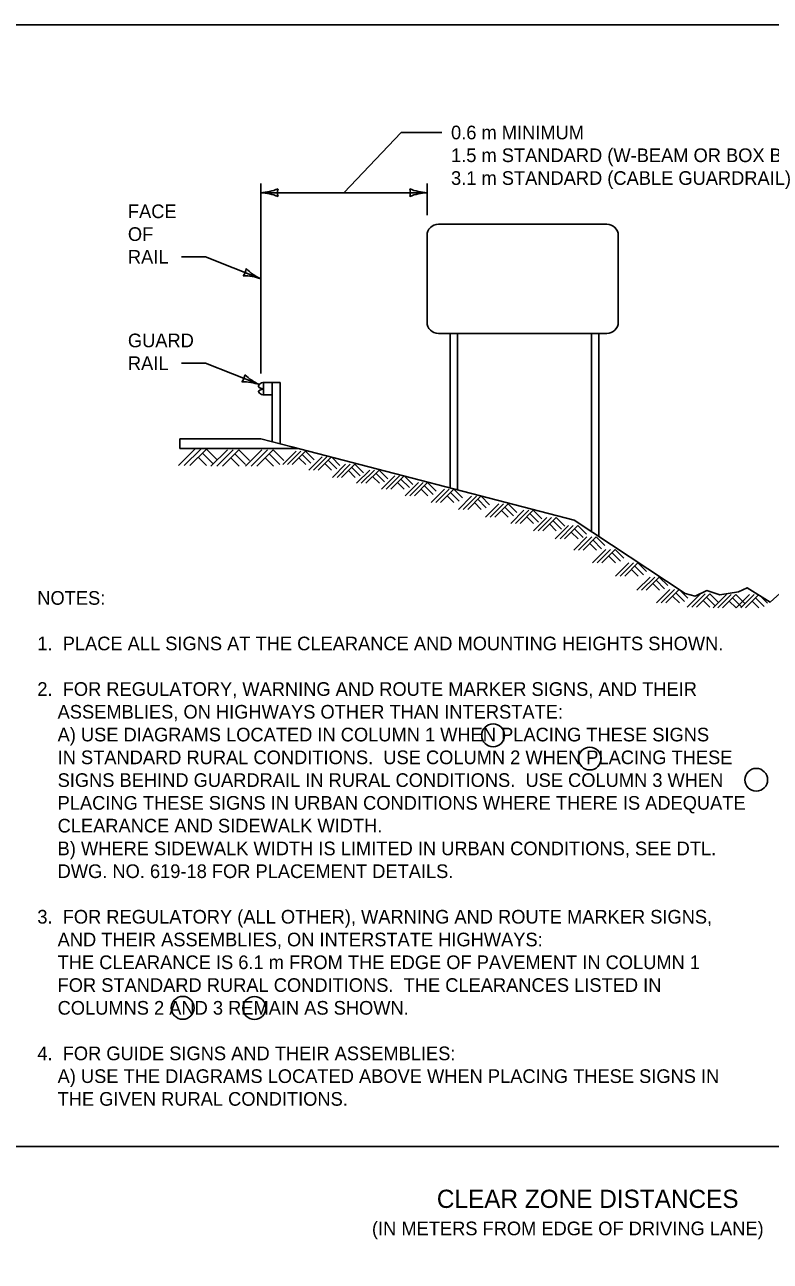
# Model space of a CAD drawing. Extents: x 49991.4 to 50021, y 49987.6 to 50011.4.
# Drawn here: x 50008.27 to 50011.55, y 49993.57 to 49999 of the extents above; entities that cross this region are included whole.
import ezdxf

# ---------------------------------------------------------------- set-up
doc = ezdxf.new("R2010")
doc.units = 0
for name, color, linetype in [('Level 1', 7, 'Continuous'), ('Level 2', 7, 'Continuous'), ('Level 3', 7, 'Continuous')]:
    doc.layers.add(name, color=color, linetype=linetype)

msp = doc.modelspace()

# ---------------------------------------------------------------- linework, layer by layer
at = {"layer": 'Level 1'}
for p, q in [((50010.8306, 49998.1235), (50010.0905, 49998.1235)), ((50010.0405, 49998.0735), (50010.0405, 49997.6934)), ((50010.8806, 49997.6934), (50010.8806, 49998.0735)), ((50010.0905, 49997.6434), (50010.8306, 49997.6434)), ((50010.1417, 49996.9646), (50010.1417, 49997.6434)), ((50010.1738, 49996.9562), (50010.1738, 49997.6434)), ((50010.7629, 49996.7725), (50010.7629, 49997.6434)), ((50010.795, 49996.7514), (50010.795, 49997.6434)), ((50009.3603, 49997.4275), (50009.3197, 49997.4275)), ((50009.3215, 49997.4275), (50009.3215, 49997.3742)), ((50009.3603, 49997.1675), (50009.3603, 49997.4275)), ((50009.3957, 49997.4275), (50009.3603, 49997.4275)), ((50009.3957, 49997.1586), (50009.3957, 49997.4275)), ((50009.3197, 49997.3742), (50009.3603, 49997.3742)), ((50008.9487, 49997.0636), (50009.0207, 49997.1356)), ((50009.31, 49997.1809), (50008.9538, 49997.1809)), ((50008.9538, 49997.1809), (50008.9538, 49997.1383)), ((50008.9538, 49997.1383), (50009.4739, 49997.1383)), ((50008.974, 49997.0636), (50009.046, 49997.1356)), ((50008.9991, 49997.0636), (50009.0711, 49997.1356)), ((50009.0711, 49997.1356), (50009.118, 49997.0888)), ((50009.0912, 49997.0606), (50009.1632, 49997.1326)), ((50009.1165, 49997.0606), (50009.1885, 49997.1326)), ((50009.1416, 49997.0606), (50009.2136, 49997.1326)), ((50009.2136, 49997.1326), (50009.2605, 49997.0858)), ((50009.2425, 49997.0606), (50009.3145, 49997.1326)), ((50009.2678, 49997.0606), (50009.3398, 49997.1326)), ((50009.2929, 49997.0606), (50009.3649, 49997.1326)), ((50009.446, 49997.1455), (50009.31, 49997.1809)), ((50009.3649, 49997.1326), (50009.4118, 49997.0858)), ((50009.446, 49997.1455), (50010.6864, 49996.8229)), ((50009.4737, 49997.1383), (50009.4737, 49997.1383)), ((50009.0355, 49997.0999), (50009.0719, 49997.0636)), ((50009.0534, 49997.1178), (50009.1002, 49997.0711)), ((50009.178, 49997.0969), (50009.2144, 49997.0606)), ((50009.1958, 49997.1148), (50009.2426, 49997.0681)), ((50009.3293, 49997.0969), (50009.3657, 49997.0606)), ((50009.3471, 49997.1148), (50009.3939, 49997.0681)), ((50009.4076, 49997.0684), (50009.4659, 49997.1267)), ((50009.4281, 49997.0684), (50009.4864, 49997.1267)), ((50009.4484, 49997.0684), (50009.5067, 49997.1267)), ((50009.4779, 49997.0979), (50009.5075, 49997.0684)), ((50009.4923, 49997.1124), (50009.5303, 49997.0745)), ((50009.5067, 49997.1267), (50009.5447, 49997.0888)), ((50009.5209, 49997.0431), (50009.5792, 49997.1014)), ((50009.5414, 49997.0431), (50009.5997, 49997.1014)), ((50009.5617, 49997.0431), (50009.6192, 49997.1005)), ((50009.6057, 49997.0871), (50009.6436, 49997.0492)), ((50009.6217, 49997.0998), (50009.658, 49997.0635)), ((50009.5912, 49997.0725), (50009.6208, 49997.0431)), ((50009.6246, 49997.0115), (50009.6829, 49997.0698)), ((50009.6451, 49997.0115), (50009.7034, 49997.0698)), ((50009.6654, 49997.0115), (50009.7237, 49997.0698)), ((50009.6949, 49997.041), (50009.7244, 49997.0115)), ((50009.7094, 49997.0555), (50009.7473, 49997.0176)), ((50009.7237, 49997.0698), (50009.7617, 49997.0319)), ((50009.731, 49996.9853), (50009.7893, 49997.0437)), ((50009.7516, 49996.9853), (50009.8099, 49997.0437)), ((50009.7719, 49996.9853), (50009.8302, 49997.0437)), ((50009.8158, 49997.0293), (50009.8537, 49996.9914)), ((50009.8302, 49997.0437), (50009.8682, 49997.0057)), ((50009.8014, 49997.0147), (50009.8309, 49996.9853)), ((50009.8405, 49996.9602), (50009.8988, 49997.0185)), ((50009.861, 49996.9602), (50009.9194, 49997.0185)), ((50009.8814, 49996.9602), (50009.9386, 49997.0174)), ((50009.9109, 49996.9896), (50009.9403, 49996.9602)), ((50009.9253, 49997.0041), (50009.9632, 49996.9664)), ((50009.9416, 49997.0166), (50009.9777, 49996.9807)), ((50009.944, 49996.9307), (50010.0023, 49996.9891)), ((50009.9646, 49996.9307), (50010.0229, 49996.9891)), ((50009.9848, 49996.9307), (50010.0431, 49996.9891)), ((50010.0287, 49996.9747), (50010.0667, 49996.9368)), ((50010.0431, 49996.9891), (50010.0812, 49996.9511)), ((50010.0143, 49996.9602), (50010.0438, 49996.9307)), ((50010.0589, 49996.9009), (50010.1172, 49996.9593)), ((50010.0795, 49996.9009), (50010.1378, 49996.9593)), ((50010.0997, 49996.9009), (50010.158, 49996.9593)), ((50010.1292, 49996.9304), (50010.1587, 49996.9009)), ((50010.1436, 49996.9449), (50010.1816, 49996.907)), ((50010.158, 49996.9593), (50010.1961, 49996.9213)), ((50010.1782, 49996.8711), (50010.2365, 49996.9295)), ((50010.1988, 49996.8711), (50010.2571, 49996.9295)), ((50010.219, 49996.8711), (50010.2771, 49996.9293)), ((50010.2629, 49996.9151), (50010.3009, 49996.8772)), ((50010.2776, 49996.9292), (50010.3154, 49996.8915)), ((50010.2485, 49996.9006), (50010.278, 49996.8711)), ((50010.2974, 49996.837), (50010.3557, 49996.8954)), ((50010.318, 49996.837), (50010.3763, 49996.8954)), ((50010.3382, 49996.837), (50010.3965, 49996.8954)), ((50010.3677, 49996.8665), (50010.3972, 49996.837)), ((50010.3821, 49996.881), (50010.4201, 49996.8431)), ((50010.3965, 49996.8954), (50010.4346, 49996.8574)), ((50010.4081, 49996.8093), (50010.4664, 49996.8677)), ((50010.4287, 49996.8093), (50010.487, 49996.8677)), ((50010.4489, 49996.8093), (50010.5072, 49996.8677)), ((50010.5072, 49996.8677), (50010.5453, 49996.8297)), ((50010.4784, 49996.8388), (50010.5079, 49996.8093)), ((50010.4928, 49996.8533), (50010.5308, 49996.8154)), ((50010.5082, 49996.7774), (50010.5665, 49996.8358)), ((50010.5288, 49996.7774), (50010.5871, 49996.8358)), ((50010.549, 49996.7774), (50010.6073, 49996.8358)), ((50010.5785, 49996.8069), (50010.608, 49996.7774)), ((50010.5929, 49996.8214), (50010.6309, 49996.7835)), ((50010.6073, 49996.8358), (50010.6454, 49996.7978)), ((50010.6864, 49996.8229), (50011.1739, 49996.5018)), ((50010.604, 49996.7412), (50010.6623, 49996.7996)), ((50010.6246, 49996.7412), (50010.6829, 49996.7996)), ((50010.6448, 49996.7412), (50010.7031, 49996.7996)), ((50010.6743, 49996.7707), (50010.7038, 49996.7412)), ((50010.6849, 49996.6922), (50010.7432, 49996.7506)), ((50010.6887, 49996.7852), (50010.7267, 49996.7473)), ((50010.7031, 49996.7996), (50010.7412, 49996.7616)), ((50010.7055, 49996.6922), (50010.7638, 49996.7506)), ((50010.7257, 49996.6922), (50010.784, 49996.7506)), ((50010.784, 49996.7506), (50010.8221, 49996.7126)), ((50010.7552, 49996.7217), (50010.7847, 49996.6922)), ((50010.768, 49996.6369), (50010.8263, 49996.6953)), ((50010.7696, 49996.7362), (50010.8076, 49996.6983)), ((50010.7886, 49996.6369), (50010.8469, 49996.6953)), ((50010.8088, 49996.6369), (50010.8671, 49996.6953)), ((50010.8671, 49996.6953), (50010.9052, 49996.6573)), ((50010.8383, 49996.6664), (50010.8678, 49996.6369)), ((50010.8527, 49996.6809), (50010.8907, 49996.643)), ((50010.868, 49996.5773), (50010.9263, 49996.6357)), ((50010.8886, 49996.5773), (50010.9469, 49996.6357)), ((50010.9088, 49996.5773), (50010.9671, 49996.6357)), ((50010.9383, 49996.6068), (50010.9678, 49996.5773)), ((50010.9527, 49996.6213), (50010.9907, 49996.5834)), ((50010.9671, 49996.6357), (50011.0052, 49996.5977)), ((50010.9617, 49996.5155), (50011.02, 49996.5739)), ((50010.9823, 49996.5155), (50011.0406, 49996.5739)), ((50011.0025, 49996.5155), (50011.0608, 49996.5739)), ((50011.032, 49996.545), (50011.0615, 49996.5155)), ((50011.0464, 49996.5595), (50011.0844, 49996.5216)), ((50011.0608, 49996.5739), (50011.0989, 49996.5359)), ((50011.0491, 49996.4601), (50011.1074, 49996.5185)), ((50011.0697, 49996.4601), (50011.128, 49996.5185)), ((50011.0899, 49996.4601), (50011.1482, 49996.5185)), ((50011.1194, 49996.4896), (50011.1489, 49996.4601)), ((50011.1338, 49996.5041), (50011.1718, 49996.4662)), ((50011.1482, 49996.5185), (50011.1863, 49996.4805)), ((50011.1831, 49996.441), (50011.2414, 49996.4994)), ((50011.2037, 49996.441), (50011.262, 49996.4994)), ((50011.2239, 49996.441), (50011.2822, 49996.4994)), ((50011.2678, 49996.485), (50011.3058, 49996.4471)), ((50011.2822, 49996.4994), (50011.3203, 49996.4614)), ((50011.2981, 49996.4389), (50011.3564, 49996.4973)), ((50011.3187, 49996.4389), (50011.377, 49996.4973)), ((50011.3389, 49996.4389), (50011.3972, 49996.4973)), ((50011.3828, 49996.4829), (50011.4208, 49996.445)), ((50011.3972, 49996.4973), (50011.4353, 49996.4593)), ((50011.3983, 49996.4389), (50011.4566, 49996.4973)), ((50011.4189, 49996.4389), (50011.4772, 49996.4973)), ((50011.4391, 49996.4389), (50011.4962, 49996.4961)), ((50011.483, 49996.4829), (50011.521, 49996.445)), ((50011.5025, 49996.4922), (50011.5355, 49996.4593)), ((50011.2534, 49996.4705), (50011.2829, 49996.441)), ((50011.3684, 49996.4684), (50011.3979, 49996.4389)), ((50011.4686, 49996.4684), (50011.4981, 49996.4389))]:
    msp.add_line(p, q, dxfattribs=at)
msp.add_lwpolyline([(49999.3835, 49998.9992), (50016.7501, 49998.9992), (50016.7501, 49987.7988), (49999.3835, 49987.7988)], close=True, dxfattribs=at)
msp.add_lwpolyline([(50011.1739, 49996.5018), (50011.2183, 49996.4891), (50011.2691, 49996.5144), (50011.3261, 49996.4954), (50011.4086, 49996.5081), (50011.4467, 49996.5271), (50011.5481, 49996.4637), (50011.6052, 49996.5144), (50011.6876, 49996.5081), (50011.7131, 49996.5017)], dxfattribs=at)
for centre, start, end in [((50010.0905, 49998.0735), 90, 180), ((50010.8305, 49998.0735), 0, 90), ((50010.0905, 49997.6934), 180, 270), ((50010.8305, 49997.6935), 270, 0)]:
    msp.add_arc(centre, 0.05, start, end, dxfattribs=at)
msp.add_spline([(50009.3197, 49997.4275), (50009.301, 49997.4169), (50009.3006, 49997.4099), (50009.3197, 49997.4008), (50009.3204, 49997.4006), (50009.3006, 49997.3894), (50009.301, 49997.3857), (50009.3197, 49997.3742)], degree=3, dxfattribs=at)
at = {"layer": 'Level 2'}
for centre in [(50010.3307, 49995.8785), (50010.7555, 49995.7767), (50011.4868, 49995.6834), (50008.9671, 49994.682), (50009.282, 49994.6811)]:
    msp.add_circle(centre, 0.0501, dxfattribs=at)
at = {"layer": 'Level 3'}
for p, q in [((50009.9272, 49998.526), (50009.6753, 49998.2617)), ((50009.9272, 49998.526), (50010.1059, 49998.526)), ((50009.31, 49997.4675), (50009.31, 49998.3017)), ((50010.0405, 49998.1635), (50010.0405, 49998.3017)), ((50009.31, 49998.2617), (50010.0405, 49998.2617)), ((50008.9614, 49997.9799), (50009.0669, 49997.9799)), ((50009.31, 49997.8836), (50009.0669, 49997.9799)), ((50008.9614, 49997.5128), (50009.0669, 49997.5128)), ((50009.3042, 49997.4187), (50009.0669, 49997.5128)), ((50008.0668, 49994.0732), (50016.7501, 49994.0732))]:
    msp.add_line(p, q, dxfattribs=at)
for centre, radius, start, end in [((50009.2985, 49998.4944), 0.233, 272.8273, 292.0772), ((50009.4382, 49998.2617), 0.0548, 162.1388, 197.8612), ((50010.0497, 49998.4838), 0.2223, 247.456, 267.6395), ((50009.9123, 49998.2617), 0.0548, 342.1388, 17.8612), ((50009.3008, 49998.0396), 0.2223, 67.456, 87.6395), ((50010.052, 49998.029), 0.233, 92.8273, 112.0772), ((50009.1914, 49997.9323), 0.0548, 319.831, 355.5533), ((50009.2323, 49997.6639), 0.233, 70.5194, 89.7693), ((50009.4028, 49998.0856), 0.2223, 225.1481, 245.3317), ((50009.185, 49997.466), 0.0548, 320.5287, 356.251), ((50009.3946, 49997.6219), 0.2223, 225.8458, 246.0294), ((50009.2292, 49997.1982), 0.233, 71.2171, 90.467)]:
    msp.add_arc(centre, radius, start, end, dxfattribs=at)

# ---------------------------------------------------------------- texts
at = {"layer": 'Level 2'}
for s, height, p in [('0.6 m MINIMUM', 0.06, (50010.1459, 49998.496)), ('1.5 m STANDARD (W-BEAM OR BOX BEAM GUARDRAIL)', 0.06, (50010.1459, 49998.396)), ('3.1 m STANDARD (CABLE GUARDRAIL) ', 0.06, (50010.1459, 49998.296)), ('FACE', 0.06, (50008.7263, 49998.1499)), ('OF', 0.06, (50008.7263, 49998.0499)), ('RAIL', 0.06, (50008.7263, 49997.9499)), ('GUARD', 0.06, (50008.7263, 49997.5828)), ('RAIL', 0.06, (50008.7263, 49997.4828)), ('NOTES:', 0.06, (50008.3284, 49996.452)), ('1.  PLACE ALL SIGNS AT THE CLEARANCE AND MOUNTING HEIGHTS SHOWN.', 0.06, (50008.3284, 49996.252)), ('2.  FOR REGULATORY, WARNING AND ROUTE MARKER SIGNS, AND THEIR', 0.06, (50008.3284, 49996.052)), ('    ASSEMBLIES, ON HIGHWAYS OTHER THAN INTERSTATE:', 0.06, (50008.3284, 49995.952)), ('    A) USE DIAGRAMS LOCATED IN COLUMN 1 WHEN PLACING THESE SIGNS', 0.06, (50008.3284, 49995.852)), ('    IN STANDARD RURAL CONDITIONS.  USE COLUMN 2 WHEN PLACING THESE', 0.06, (50008.3284, 49995.752)), ('    SIGNS BEHIND GUARDRAIL IN RURAL CONDITIONS.  USE COLUMN 3 WHEN', 0.06, (50008.3284, 49995.652)), ('    PLACING THESE SIGNS IN URBAN CONDITIONS WHERE THERE IS ADEQUATE', 0.06, (50008.3284, 49995.552)), ('    CLEARANCE AND SIDEWALK WIDTH.', 0.06, (50008.3284, 49995.452)), ('    B) WHERE SIDEWALK WIDTH IS LIMITED IN URBAN CONDITIONS, SEE DTL.', 0.06, (50008.3284, 49995.352)), ('    DWG. NO. 619-18 FOR PLACEMENT DETAILS.', 0.06, (50008.3284, 49995.252)), ('3.  FOR REGULATORY (ALL OTHER), WARNING AND ROUTE MARKER SIGNS,', 0.06, (50008.3284, 49995.052)), ('    AND THEIR ASSEMBLIES, ON INTERSTATE HIGHWAYS:', 0.06, (50008.3284, 49994.952)), ('    THE CLEARANCE IS 6.1 m FROM THE EDGE OF PAVEMENT IN COLUMN 1', 0.06, (50008.3284, 49994.852)), ('    FOR STANDARD RURAL CONDITIONS.  THE CLEARANCES LISTED IN', 0.06, (50008.3284, 49994.752)), ('    COLUMNS 2 AND 3 REMAIN AS SHOWN.', 0.06, (50008.3284, 49994.652)), ('4.  FOR GUIDE SIGNS AND THEIR ASSEMBLIES:', 0.06, (50008.3284, 49994.452)), ('    A) USE THE DIAGRAMS LOCATED ABOVE WHEN PLACING THESE SIGNS IN', 0.06, (50008.3284, 49994.352)), ('    THE GIVEN RURAL CONDITIONS.    ', 0.06, (50008.3284, 49994.252)), ('CLEAR ZONE DISTANCES', 0.08, (50010.0836, 49993.8033)), ('(IN METERS FROM EDGE OF DRIVING LANE)', 0.06, (50009.7985, 49993.6833))]:
    msp.add_text(s, height=height, dxfattribs=at).set_placement(p)

doc.saveas('drawing.dxf')
